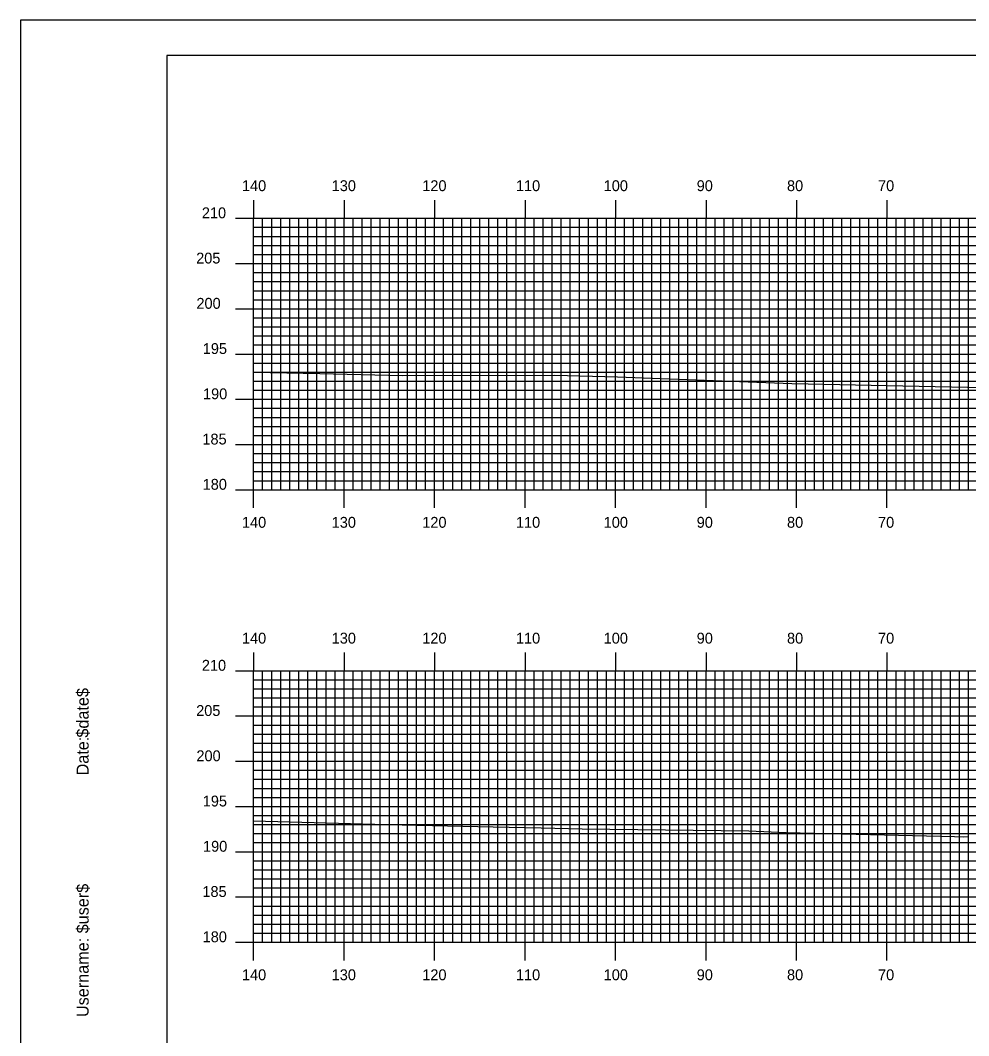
# Model space of a CAD drawing. Extents: x 1807438 to 1807782, y 442591 to 442811.
# Drawn here: x 1807438.5 to 1807543.3, y 442698.3 to 442810.5 of the extents above; entities that cross this region are included whole.
import ezdxf

# ---------------------------------------------------------------- set-up
doc = ezdxf.new("R2010")
doc.units = 0
for name, color, linetype in [('BORDER', 7, 'Continuous'), ('H_V ANNOTATION', 7, 'Continuous'), ('MAJOR', 7, 'Continuous'), ('MINOR', 7, 'Continuous'), ('PLOT BOUNDARY', 7, 'Continuous'), ('S_Roadway_Centerline', 7, 'Continuous')]:
    doc.layers.add(name, color=color, linetype=linetype)

msp = doc.modelspace()

# ---------------------------------------------------------------- linework, layer by layer
at = {"layer": 'BORDER'}
msp.add_lwpolyline([(1807454.67, 442596.67), (1807774.67, 442596.67), (1807774.67, 442806.67), (1807454.67, 442806.67)], close=True, dxfattribs=at)
at = {"layer": 'MAJOR'}
for p, q in [((1807464.27, 442790.67), (1807464.27, 442788.67)), ((1807474.27, 442790.67), (1807474.27, 442788.67)), ((1807484.27, 442790.67), (1807484.27, 442788.67)), ((1807494.27, 442790.67), (1807494.27, 442788.67)), ((1807504.27, 442790.67), (1807504.27, 442788.67)), ((1807514.27, 442790.67), (1807514.27, 442788.67)), ((1807524.27, 442790.67), (1807524.27, 442788.67)), ((1807534.27, 442790.67), (1807534.27, 442788.67)), ((1807462.27, 442788.67), (1807464.27, 442788.67)), ((1807464.27, 442788.67), (1807744.27, 442788.67)), ((1807464.27, 442758.67), (1807464.27, 442788.67)), ((1807464.27, 442758.67), (1807464.27, 442788.67)), ((1807464.27, 442788.67), (1807744.27, 442788.67)), ((1807474.27, 442758.67), (1807474.27, 442788.67)), ((1807484.27, 442758.67), (1807484.27, 442788.67)), ((1807494.27, 442758.67), (1807494.27, 442788.67)), ((1807504.27, 442758.67), (1807504.27, 442788.67)), ((1807514.27, 442758.67), (1807514.27, 442788.67)), ((1807524.27, 442758.67), (1807524.27, 442788.67)), ((1807534.27, 442758.67), (1807534.27, 442788.67)), ((1807462.27, 442783.67), (1807464.27, 442783.67)), ((1807464.27, 442783.67), (1807744.27, 442783.67)), ((1807462.27, 442778.67), (1807464.27, 442778.67)), ((1807464.27, 442778.67), (1807744.27, 442778.67)), ((1807462.27, 442773.67), (1807464.27, 442773.67)), ((1807464.27, 442773.67), (1807744.27, 442773.67)), ((1807462.27, 442768.67), (1807464.27, 442768.67)), ((1807464.27, 442768.67), (1807744.27, 442768.67)), ((1807462.27, 442763.67), (1807464.27, 442763.67)), ((1807464.27, 442763.67), (1807744.27, 442763.67)), ((1807462.27, 442758.67), (1807464.27, 442758.67)), ((1807464.27, 442758.67), (1807744.27, 442758.67)), ((1807464.27, 442758.67), (1807744.27, 442758.67)), ((1807464.27, 442756.66), (1807464.27, 442758.67)), ((1807474.27, 442756.66), (1807474.27, 442758.67)), ((1807484.27, 442756.66), (1807484.27, 442758.67)), ((1807494.27, 442756.66), (1807494.27, 442758.67)), ((1807504.27, 442756.66), (1807504.27, 442758.67)), ((1807514.27, 442756.66), (1807514.27, 442758.67)), ((1807524.27, 442756.66), (1807524.27, 442758.67)), ((1807534.27, 442756.66), (1807534.27, 442758.67)), ((1807464.27, 442740.67), (1807464.27, 442738.67)), ((1807474.27, 442740.67), (1807474.27, 442738.67)), ((1807484.27, 442740.67), (1807484.27, 442738.67)), ((1807494.27, 442740.67), (1807494.27, 442738.67)), ((1807504.27, 442740.67), (1807504.27, 442738.67)), ((1807514.27, 442740.67), (1807514.27, 442738.67)), ((1807524.27, 442740.67), (1807524.27, 442738.67)), ((1807534.27, 442740.67), (1807534.27, 442738.67)), ((1807462.27, 442738.67), (1807464.27, 442738.67)), ((1807464.27, 442738.67), (1807744.27, 442738.67)), ((1807464.27, 442708.67), (1807464.27, 442738.67)), ((1807464.27, 442708.67), (1807464.27, 442738.67)), ((1807464.27, 442738.67), (1807744.27, 442738.67)), ((1807474.27, 442708.67), (1807474.27, 442738.67)), ((1807484.27, 442708.67), (1807484.27, 442738.67)), ((1807494.27, 442708.67), (1807494.27, 442738.67)), ((1807504.27, 442708.67), (1807504.27, 442738.67)), ((1807514.27, 442708.67), (1807514.27, 442738.67)), ((1807524.27, 442708.67), (1807524.27, 442738.67)), ((1807534.27, 442708.67), (1807534.27, 442738.67)), ((1807462.27, 442733.67), (1807464.27, 442733.67)), ((1807464.27, 442733.67), (1807744.27, 442733.67)), ((1807462.27, 442728.67), (1807464.27, 442728.67)), ((1807464.27, 442728.67), (1807744.27, 442728.67)), ((1807462.27, 442723.67), (1807464.27, 442723.67)), ((1807464.27, 442723.67), (1807744.27, 442723.67)), ((1807462.27, 442718.67), (1807464.27, 442718.67)), ((1807464.27, 442718.67), (1807744.27, 442718.67)), ((1807462.27, 442713.67), (1807464.27, 442713.67)), ((1807464.27, 442713.67), (1807744.27, 442713.67)), ((1807462.27, 442708.67), (1807464.27, 442708.67)), ((1807464.27, 442708.67), (1807744.27, 442708.67)), ((1807464.27, 442708.67), (1807744.27, 442708.67)), ((1807464.27, 442706.66), (1807464.27, 442708.67)), ((1807474.27, 442706.66), (1807474.27, 442708.67)), ((1807484.27, 442706.66), (1807484.27, 442708.67)), ((1807494.27, 442706.66), (1807494.27, 442708.67)), ((1807504.27, 442706.66), (1807504.27, 442708.67)), ((1807514.27, 442706.66), (1807514.27, 442708.67)), ((1807524.27, 442706.66), (1807524.27, 442708.67)), ((1807534.27, 442706.66), (1807534.27, 442708.67))]:
    msp.add_line(p, q, dxfattribs=at)
at = {"layer": 'MINOR'}
for p, q in [((1807465.27, 442758.67), (1807465.27, 442788.67)), ((1807466.27, 442758.67), (1807466.27, 442788.67)), ((1807467.27, 442758.67), (1807467.27, 442788.67)), ((1807468.27, 442758.67), (1807468.27, 442788.67)), ((1807469.27, 442758.67), (1807469.27, 442788.67)), ((1807470.27, 442758.67), (1807470.27, 442788.67)), ((1807471.27, 442758.67), (1807471.27, 442788.67)), ((1807472.27, 442758.67), (1807472.27, 442788.67)), ((1807473.27, 442758.67), (1807473.27, 442788.67)), ((1807475.27, 442758.67), (1807475.27, 442788.67)), ((1807476.27, 442758.67), (1807476.27, 442788.67)), ((1807477.27, 442758.67), (1807477.27, 442788.67)), ((1807478.27, 442758.67), (1807478.27, 442788.67)), ((1807479.27, 442758.67), (1807479.27, 442788.67)), ((1807480.27, 442758.67), (1807480.27, 442788.67)), ((1807481.27, 442758.67), (1807481.27, 442788.67)), ((1807482.27, 442758.67), (1807482.27, 442788.67)), ((1807483.27, 442758.67), (1807483.27, 442788.67)), ((1807485.27, 442758.67), (1807485.27, 442788.67)), ((1807486.27, 442758.67), (1807486.27, 442788.67)), ((1807487.27, 442758.67), (1807487.27, 442788.67)), ((1807488.27, 442758.67), (1807488.27, 442788.67)), ((1807489.27, 442758.67), (1807489.27, 442788.67)), ((1807490.27, 442758.67), (1807490.27, 442788.67)), ((1807491.27, 442758.67), (1807491.27, 442788.67)), ((1807492.27, 442758.67), (1807492.27, 442788.67)), ((1807493.27, 442758.67), (1807493.27, 442788.67)), ((1807495.27, 442758.67), (1807495.27, 442788.67)), ((1807496.27, 442758.67), (1807496.27, 442788.67)), ((1807497.27, 442758.67), (1807497.27, 442788.67)), ((1807498.27, 442758.67), (1807498.27, 442788.67)), ((1807499.27, 442758.67), (1807499.27, 442788.67)), ((1807500.27, 442758.67), (1807500.27, 442788.67)), ((1807501.27, 442758.67), (1807501.27, 442788.67)), ((1807502.27, 442758.67), (1807502.27, 442788.67)), ((1807503.27, 442758.67), (1807503.27, 442788.67)), ((1807505.27, 442758.67), (1807505.27, 442788.67)), ((1807506.27, 442758.67), (1807506.27, 442788.67)), ((1807507.27, 442758.67), (1807507.27, 442788.67)), ((1807508.27, 442758.67), (1807508.27, 442788.67)), ((1807509.27, 442758.67), (1807509.27, 442788.67)), ((1807510.27, 442758.67), (1807510.27, 442788.67)), ((1807511.27, 442758.67), (1807511.27, 442788.67)), ((1807512.27, 442758.67), (1807512.27, 442788.67)), ((1807513.27, 442758.67), (1807513.27, 442788.67)), ((1807515.27, 442758.67), (1807515.27, 442788.67)), ((1807516.27, 442758.67), (1807516.27, 442788.67)), ((1807517.27, 442758.67), (1807517.27, 442788.67)), ((1807518.27, 442758.67), (1807518.27, 442788.67)), ((1807519.27, 442758.67), (1807519.27, 442788.67)), ((1807520.27, 442758.67), (1807520.27, 442788.67)), ((1807521.27, 442758.67), (1807521.27, 442788.67)), ((1807522.27, 442758.67), (1807522.27, 442788.67)), ((1807523.27, 442758.67), (1807523.27, 442788.67)), ((1807525.27, 442758.67), (1807525.27, 442788.67)), ((1807526.27, 442758.67), (1807526.27, 442788.67)), ((1807527.27, 442758.67), (1807527.27, 442788.67)), ((1807528.27, 442758.67), (1807528.27, 442788.67)), ((1807529.27, 442758.67), (1807529.27, 442788.67)), ((1807530.27, 442758.67), (1807530.27, 442788.67)), ((1807531.27, 442758.67), (1807531.27, 442788.67)), ((1807532.27, 442758.67), (1807532.27, 442788.67)), ((1807533.27, 442758.67), (1807533.27, 442788.67)), ((1807535.27, 442758.67), (1807535.27, 442788.67)), ((1807536.27, 442758.67), (1807536.27, 442788.67)), ((1807537.27, 442758.67), (1807537.27, 442788.67)), ((1807538.27, 442758.67), (1807538.27, 442788.67)), ((1807539.27, 442758.67), (1807539.27, 442788.67)), ((1807540.27, 442758.67), (1807540.27, 442788.67)), ((1807541.27, 442758.67), (1807541.27, 442788.67)), ((1807542.27, 442758.67), (1807542.27, 442788.67)), ((1807543.27, 442758.67), (1807543.27, 442788.67)), ((1807464.27, 442787.67), (1807744.27, 442787.67)), ((1807464.27, 442787.67), (1807466.28, 442787.67)), ((1807464.27, 442786.67), (1807744.27, 442786.67)), ((1807464.27, 442786.67), (1807466.28, 442786.67)), ((1807464.27, 442785.67), (1807744.27, 442785.67)), ((1807464.27, 442785.67), (1807466.28, 442785.67)), ((1807464.27, 442784.67), (1807744.27, 442784.67)), ((1807464.27, 442784.67), (1807466.28, 442784.67)), ((1807464.27, 442782.67), (1807744.27, 442782.67)), ((1807464.27, 442782.67), (1807466.28, 442782.67)), ((1807464.27, 442781.67), (1807744.27, 442781.67)), ((1807464.27, 442781.67), (1807466.28, 442781.67)), ((1807464.27, 442780.67), (1807744.27, 442780.67)), ((1807464.27, 442780.67), (1807466.28, 442780.67)), ((1807464.27, 442779.67), (1807744.27, 442779.67)), ((1807464.27, 442779.67), (1807466.28, 442779.67)), ((1807464.27, 442777.67), (1807744.27, 442777.67)), ((1807464.27, 442777.67), (1807466.28, 442777.67)), ((1807464.27, 442776.67), (1807744.27, 442776.67)), ((1807464.27, 442776.67), (1807466.28, 442776.67)), ((1807464.27, 442775.67), (1807744.27, 442775.67)), ((1807464.27, 442775.67), (1807466.28, 442775.67)), ((1807464.27, 442774.67), (1807744.27, 442774.67)), ((1807464.27, 442774.67), (1807466.28, 442774.67)), ((1807464.27, 442772.67), (1807744.27, 442772.67)), ((1807464.27, 442772.67), (1807466.28, 442772.67)), ((1807464.27, 442771.67), (1807744.27, 442771.67)), ((1807464.27, 442771.67), (1807466.28, 442771.67)), ((1807464.27, 442770.67), (1807744.27, 442770.67)), ((1807464.27, 442770.67), (1807466.28, 442770.67)), ((1807464.27, 442769.67), (1807744.27, 442769.67)), ((1807464.27, 442769.67), (1807466.28, 442769.67)), ((1807464.27, 442767.67), (1807744.27, 442767.67)), ((1807464.27, 442767.67), (1807466.28, 442767.67)), ((1807464.27, 442766.67), (1807744.27, 442766.67)), ((1807464.27, 442766.67), (1807466.28, 442766.67)), ((1807464.27, 442765.67), (1807744.27, 442765.67)), ((1807464.27, 442765.67), (1807466.28, 442765.67)), ((1807464.27, 442764.67), (1807744.27, 442764.67)), ((1807464.27, 442764.67), (1807466.28, 442764.67)), ((1807464.27, 442762.67), (1807744.27, 442762.67)), ((1807464.27, 442762.67), (1807466.28, 442762.67)), ((1807464.27, 442761.67), (1807744.27, 442761.67)), ((1807464.27, 442761.67), (1807466.28, 442761.67)), ((1807464.27, 442760.67), (1807744.27, 442760.67)), ((1807464.27, 442760.67), (1807466.28, 442760.67)), ((1807464.27, 442759.67), (1807744.27, 442759.67)), ((1807464.27, 442759.67), (1807466.28, 442759.67)), ((1807465.27, 442708.67), (1807465.27, 442738.67)), ((1807466.27, 442708.67), (1807466.27, 442738.67)), ((1807467.27, 442708.67), (1807467.27, 442738.67)), ((1807468.27, 442708.67), (1807468.27, 442738.67)), ((1807469.27, 442708.67), (1807469.27, 442738.67)), ((1807470.27, 442708.67), (1807470.27, 442738.67)), ((1807471.27, 442708.67), (1807471.27, 442738.67)), ((1807472.27, 442708.67), (1807472.27, 442738.67)), ((1807473.27, 442708.67), (1807473.27, 442738.67)), ((1807475.27, 442708.67), (1807475.27, 442738.67)), ((1807476.27, 442708.67), (1807476.27, 442738.67)), ((1807477.27, 442708.67), (1807477.27, 442738.67)), ((1807478.27, 442708.67), (1807478.27, 442738.67)), ((1807479.27, 442708.67), (1807479.27, 442738.67)), ((1807480.27, 442708.67), (1807480.27, 442738.67)), ((1807481.27, 442708.67), (1807481.27, 442738.67)), ((1807482.27, 442708.67), (1807482.27, 442738.67)), ((1807483.27, 442708.67), (1807483.27, 442738.67)), ((1807485.27, 442708.67), (1807485.27, 442738.67)), ((1807486.27, 442708.67), (1807486.27, 442738.67)), ((1807487.27, 442708.67), (1807487.27, 442738.67)), ((1807488.27, 442708.67), (1807488.27, 442738.67)), ((1807489.27, 442708.67), (1807489.27, 442738.67)), ((1807490.27, 442708.67), (1807490.27, 442738.67)), ((1807491.27, 442708.67), (1807491.27, 442738.67)), ((1807492.27, 442708.67), (1807492.27, 442738.67)), ((1807493.27, 442708.67), (1807493.27, 442738.67)), ((1807495.27, 442708.67), (1807495.27, 442738.67)), ((1807496.27, 442708.67), (1807496.27, 442738.67)), ((1807497.27, 442708.67), (1807497.27, 442738.67)), ((1807498.27, 442708.67), (1807498.27, 442738.67)), ((1807499.27, 442708.67), (1807499.27, 442738.67)), ((1807500.27, 442708.67), (1807500.27, 442738.67)), ((1807501.27, 442708.67), (1807501.27, 442738.67)), ((1807502.27, 442708.67), (1807502.27, 442738.67)), ((1807503.27, 442708.67), (1807503.27, 442738.67)), ((1807505.27, 442708.67), (1807505.27, 442738.67)), ((1807506.27, 442708.67), (1807506.27, 442738.67)), ((1807507.27, 442708.67), (1807507.27, 442738.67)), ((1807508.27, 442708.67), (1807508.27, 442738.67)), ((1807509.27, 442708.67), (1807509.27, 442738.67)), ((1807510.27, 442708.67), (1807510.27, 442738.67)), ((1807511.27, 442708.67), (1807511.27, 442738.67)), ((1807512.27, 442708.67), (1807512.27, 442738.67)), ((1807513.27, 442708.67), (1807513.27, 442738.67)), ((1807515.27, 442708.67), (1807515.27, 442738.67)), ((1807516.27, 442708.67), (1807516.27, 442738.67)), ((1807517.27, 442708.67), (1807517.27, 442738.67)), ((1807518.27, 442708.67), (1807518.27, 442738.67)), ((1807519.27, 442708.67), (1807519.27, 442738.67)), ((1807520.27, 442708.67), (1807520.27, 442738.67)), ((1807521.27, 442708.67), (1807521.27, 442738.67)), ((1807522.27, 442708.67), (1807522.27, 442738.67)), ((1807523.27, 442708.67), (1807523.27, 442738.67)), ((1807525.27, 442708.67), (1807525.27, 442738.67)), ((1807526.27, 442708.67), (1807526.27, 442738.67)), ((1807527.27, 442708.67), (1807527.27, 442738.67)), ((1807528.27, 442708.67), (1807528.27, 442738.67)), ((1807529.27, 442708.67), (1807529.27, 442738.67)), ((1807530.27, 442708.67), (1807530.27, 442738.67)), ((1807531.27, 442708.67), (1807531.27, 442738.67)), ((1807532.27, 442708.67), (1807532.27, 442738.67)), ((1807533.27, 442708.67), (1807533.27, 442738.67)), ((1807535.27, 442708.67), (1807535.27, 442738.67)), ((1807536.27, 442708.67), (1807536.27, 442738.67)), ((1807537.27, 442708.67), (1807537.27, 442738.67)), ((1807538.27, 442708.67), (1807538.27, 442738.67)), ((1807539.27, 442708.67), (1807539.27, 442738.67)), ((1807540.27, 442708.67), (1807540.27, 442738.67)), ((1807541.27, 442708.67), (1807541.27, 442738.67)), ((1807542.27, 442708.67), (1807542.27, 442738.67)), ((1807543.27, 442708.67), (1807543.27, 442738.67)), ((1807464.27, 442737.67), (1807744.27, 442737.67)), ((1807464.27, 442737.67), (1807466.28, 442737.67)), ((1807464.27, 442736.67), (1807744.27, 442736.67)), ((1807464.27, 442736.67), (1807466.28, 442736.67)), ((1807464.27, 442735.67), (1807744.27, 442735.67)), ((1807464.27, 442735.67), (1807466.28, 442735.67)), ((1807464.27, 442734.67), (1807744.27, 442734.67)), ((1807464.27, 442734.67), (1807466.28, 442734.67)), ((1807464.27, 442732.67), (1807744.27, 442732.67)), ((1807464.27, 442732.67), (1807466.28, 442732.67)), ((1807464.27, 442731.67), (1807744.27, 442731.67)), ((1807464.27, 442731.67), (1807466.28, 442731.67)), ((1807464.27, 442730.67), (1807744.27, 442730.67)), ((1807464.27, 442730.67), (1807466.28, 442730.67)), ((1807464.27, 442729.67), (1807744.27, 442729.67)), ((1807464.27, 442729.67), (1807466.28, 442729.67)), ((1807464.27, 442727.67), (1807744.27, 442727.67)), ((1807464.27, 442727.67), (1807466.28, 442727.67)), ((1807464.27, 442726.67), (1807744.27, 442726.67)), ((1807464.27, 442726.67), (1807466.28, 442726.67)), ((1807464.27, 442725.67), (1807744.27, 442725.67)), ((1807464.27, 442725.67), (1807466.28, 442725.67)), ((1807464.27, 442724.67), (1807744.27, 442724.67)), ((1807464.27, 442724.67), (1807466.28, 442724.67)), ((1807464.27, 442722.67), (1807744.27, 442722.67)), ((1807464.27, 442722.67), (1807466.28, 442722.67)), ((1807464.27, 442721.67), (1807744.27, 442721.67)), ((1807464.27, 442721.67), (1807466.28, 442721.67)), ((1807464.27, 442720.67), (1807744.27, 442720.67)), ((1807464.27, 442720.67), (1807466.28, 442720.67)), ((1807464.27, 442719.67), (1807744.27, 442719.67)), ((1807464.27, 442719.67), (1807466.28, 442719.67)), ((1807464.27, 442717.67), (1807744.27, 442717.67)), ((1807464.27, 442717.67), (1807466.28, 442717.67)), ((1807464.27, 442716.67), (1807744.27, 442716.67)), ((1807464.27, 442716.67), (1807466.28, 442716.67)), ((1807464.27, 442715.67), (1807744.27, 442715.67)), ((1807464.27, 442715.67), (1807466.28, 442715.67)), ((1807464.27, 442714.67), (1807744.27, 442714.67)), ((1807464.27, 442714.67), (1807466.28, 442714.67)), ((1807464.27, 442712.67), (1807744.27, 442712.67)), ((1807464.27, 442712.67), (1807466.28, 442712.67)), ((1807464.27, 442711.67), (1807744.27, 442711.67)), ((1807464.27, 442711.67), (1807466.28, 442711.67)), ((1807464.27, 442710.67), (1807744.27, 442710.67)), ((1807464.27, 442710.67), (1807466.28, 442710.67)), ((1807464.27, 442709.67), (1807744.27, 442709.67)), ((1807464.27, 442709.67), (1807466.28, 442709.67))]:
    msp.add_line(p, q, dxfattribs=at)
at = {"layer": 'PLOT BOUNDARY'}
msp.add_lwpolyline([(1807438.49, 442590.55), (1807778.49, 442590.55), (1807778.49, 442810.55), (1807438.49, 442810.55)], close=True, dxfattribs=at)
at = {"layer": 'S_Roadway_Centerline'}
for points in [[(1807464.27, 442771.67), (1807471.57, 442771.5), (1807480.68, 442771.28), (1807497.56, 442771.33), (1807504.47, 442771.15), (1807523.77, 442770.42), (1807525.54, 442770.39), (1807536.03, 442770.16), (1807544.98, 442769.98)], [(1807464.27, 442722.07), (1807479.01, 442721.69), (1807490.76, 442721.43), (1807496.04, 442721.31), (1807500.57, 442721.19), (1807519.01, 442720.97), (1807523.12, 442720.79), (1807541.73, 442720.34), (1807542.68, 442720.33), (1807543.32, 442720.35)]]:
    msp.add_lwpolyline(points, dxfattribs=at)

# ---------------------------------------------------------------- texts
at = {"layer": 'BORDER'}
for s, p in [('$date$', (1807446.04, 442731.28)), ('Date:', (1807446.04, 442727.1)), ('$user$', (1807446.04, 442709.65)), ('Username:', (1807446.04, 442700.4))]:
    msp.add_text(s, height=1.339, rotation=90, dxfattribs=at).set_placement(p)
at = {"layer": 'H_V ANNOTATION'}
for s, p in [('140', (1807462.98, 442791.67)), ('130', (1807472.9, 442791.67)), ('120', (1807482.91, 442791.67)), ('110', (1807493.26, 442791.67)), ('100', (1807502.96, 442791.67)), ('90', (1807513.24, 442791.67)), ('80', (1807523.22, 442791.67)), ('70', (1807533.28, 442791.67)), ('210', (1807458.55, 442788.67)), ('205', (1807457.92, 442783.67)), ('200', (1807457.95, 442778.67)), ('195', (1807458.65, 442773.67)), ('190', (1807458.68, 442768.67)), ('185', (1807458.61, 442763.67)), ('180', (1807458.64, 442758.67)), ('140', (1807462.98, 442754.47)), ('130', (1807472.9, 442754.47)), ('120', (1807482.91, 442754.47)), ('110', (1807493.26, 442754.47)), ('100', (1807502.96, 442754.47)), ('90', (1807513.24, 442754.47)), ('80', (1807523.22, 442754.47)), ('70', (1807533.28, 442754.47)), ('140', (1807462.98, 442741.67)), ('130', (1807472.9, 442741.67)), ('120', (1807482.91, 442741.67)), ('110', (1807493.26, 442741.67)), ('100', (1807502.96, 442741.67)), ('90', (1807513.24, 442741.67)), ('80', (1807523.22, 442741.67)), ('70', (1807533.28, 442741.67)), ('210', (1807458.55, 442738.67)), ('205', (1807457.92, 442733.67)), ('200', (1807457.95, 442728.67)), ('195', (1807458.65, 442723.67)), ('190', (1807458.68, 442718.67)), ('185', (1807458.61, 442713.67)), ('180', (1807458.64, 442708.67)), ('140', (1807462.98, 442704.47)), ('130', (1807472.9, 442704.47)), ('120', (1807482.91, 442704.47)), ('110', (1807493.26, 442704.47)), ('100', (1807502.96, 442704.47)), ('90', (1807513.24, 442704.47)), ('80', (1807523.22, 442704.47)), ('70', (1807533.28, 442704.47))]:
    msp.add_text(s, height=1.2, dxfattribs=at).set_placement(p)
at = {"layer": 'MAJOR'}
for p in [(1807464.26, 442758.67), (1807464.26, 442708.67)]:
    msp.add_text('-', height=0.012, dxfattribs=at).set_placement(p)

doc.saveas('drawing.dxf')
